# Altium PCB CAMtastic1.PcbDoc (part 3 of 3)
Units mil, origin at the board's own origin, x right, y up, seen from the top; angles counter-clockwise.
Board outline 2031.62 x 893.83 mil, 4 copper layers (Top Layer, Mid-Layer 1, Mid-Layer 2, Bottom Layer); 0 components, 63 nets, 248 pads, 0 vias.
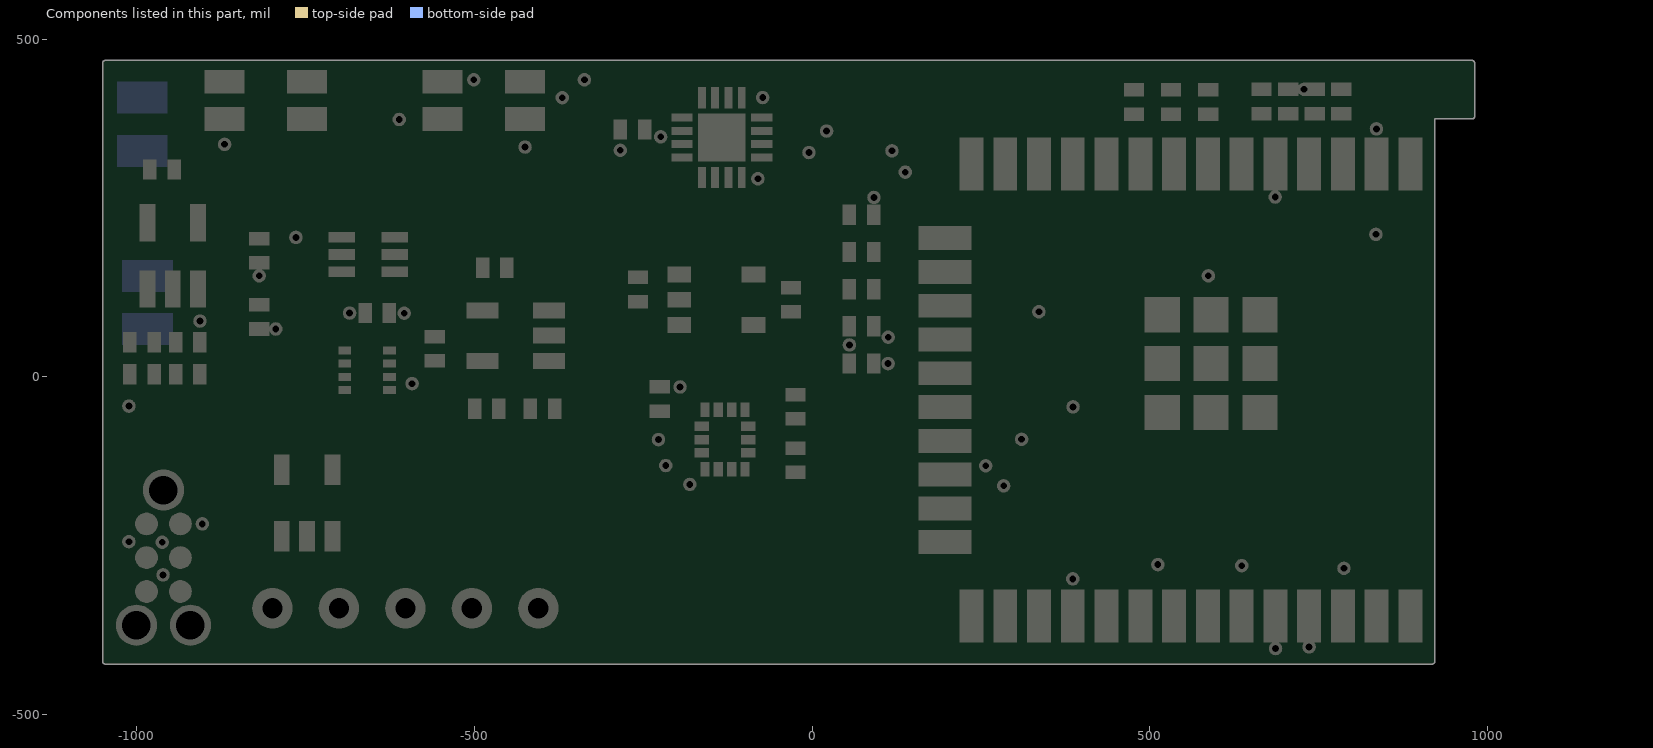
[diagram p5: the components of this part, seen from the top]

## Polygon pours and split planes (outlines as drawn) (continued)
no net on Mid-Layer 1 (solid, pour order 33): -816.2,-383.52 -782.23,-383.52 -758.21,-359.5 -758.21,-325.54 -782.23,-301.52 -816.2,-301.52 -840.21,-325.54 -840.21,-359.5
no net on Mid-Layer 1 (solid, pour order 32): -1001.14,-150.94 -1001.14,-184.5 -977.41,-208.23 -943.85,-208.23 -920.12,-184.5 -920.12,-150.94 -943.85,-127.21 -977.41,-127.21
$Net11 on Mid-Layer 1 (solid, pour order 31): 44 vertices, not listed, extent -1032.68,-407.26 962.94,450.57
no net on Mid-Layer 1 (solid, pour order 30): 503.53,-298 520.1,-298 531.81,-286.29 531.81,-269.72 520.1,-258 503.53,-258 491.81,-269.72 491.81,-286.29
no net on Mid-Layer 1 (solid, pour order 29): -1020.1,-264.09 -1003.53,-264.09 -991.81,-252.38 -991.81,-235.81 -1003.53,-224.09 -1020.1,-224.09 -1031.81,-235.81 -1031.81,-252.38
no net on Mid-Layer 1 (solid, pour order 28): 779.12,-303.46 795.69,-303.46 807.4,-291.75 807.4,-275.18 795.69,-263.47 779.12,-263.47 767.4,-275.18 767.4,-291.75
no net on Mid-Layer 1 (solid, pour order 27): 627.73,-299.53 644.3,-299.53 656.01,-287.81 656.01,-271.24 644.3,-259.53 627.73,-259.53 616.02,-271.24 616.02,-287.81
no net on Mid-Layer 1 (solid, pour order 26): 132.48,67.05 132.48,50.48 121.12,39.12 132.33,27.91 132.33,11.34 120.62,-0.37 104.05,-0.37 92.33,11.34 92.33,27.91 103.69,39.27 92.48,50.48 92.48,67.05 104.2,78.77 120.76,78.77
no net on Mid-Layer 1 (solid, pour order 25): 12.99,344.01 29.56,344.01 41.28,355.72 41.28,372.29 29.56,384.01 12.99,384.01 1.28,372.29 1.28,355.72
no net on Mid-Layer 1 (solid, pour order 24): -13.06,312.17 3.51,312.17 15.23,323.89 15.23,340.45 3.51,352.17 -13.06,352.17 -24.77,340.45 -24.77,323.89
no net on Mid-Layer 1 (solid, pour order 23): 17 vertices, not listed, extent 98.11,283.15 157.79,354.65
no net on Mid-Layer 1 (solid, pour order 22): 677.25,246.32 693.82,246.32 705.53,258.04 705.53,274.61 693.82,286.32 677.25,286.32 665.53,274.61 665.53,258.04
no net on Mid-Layer 1 (solid, pour order 21): 83.18,245.6 99.75,245.6 111.46,257.32 111.46,273.88 99.75,285.6 83.18,285.6 71.47,273.88 71.47,257.32
no net on Mid-Layer 1 (solid, pour order 20): -433.49,320.32 -416.92,320.32 -405.21,332.04 -405.21,348.61 -416.92,360.32 -433.49,360.32 -445.21,348.61 -445.21,332.04
no net on Mid-Layer 1 (solid, pour order 19): -88.65,273.32 -72.08,273.32 -60.36,285.04 -60.36,301.6 -72.08,313.32 -88.65,313.32 -100.36,301.6 -100.36,285.04
no net on Mid-Layer 2 (solid, pour order 116): 627.73,-299.53 644.3,-299.53 656.01,-287.81 656.01,-271.24 644.3,-259.53 627.73,-259.53 616.02,-271.24 616.02,-287.81
no net on Mid-Layer 2 (solid, pour order 115): 779.12,-303.46 795.69,-303.46 807.4,-291.75 807.4,-275.18 795.69,-263.47 779.12,-263.47 767.4,-275.18 767.4,-291.75
no net on Mid-Layer 2 (solid, pour order 114): -1020.1,-264.09 -1003.53,-264.09 -991.81,-252.38 -991.81,-235.81 -1003.53,-224.09 -1020.1,-224.09 -1031.81,-235.81 -1031.81,-252.38
no net on Mid-Layer 2 (solid, pour order 113): 503.53,-298 520.1,-298 531.81,-286.29 531.81,-269.72 520.1,-258 503.53,-258 491.81,-269.72 491.81,-286.29
$Net0 on Mid-Layer 2 (solid, pour order 112): 44 vertices, not listed, extent -1032.68,-407.26 962.94,450.57
no net on Mid-Layer 2 (solid, pour order 111): -1001.14,-150.94 -1001.14,-184.5 -977.41,-208.23 -943.85,-208.23 -920.12,-184.5 -920.12,-150.94 -943.85,-127.21 -977.41,-127.21
no net on Mid-Layer 2 (solid, pour order 110): -717.77,-383.52 -683.8,-383.52 -659.79,-359.5 -659.79,-325.54 -683.8,-301.52 -717.77,-301.52 -741.79,-325.54 -741.79,-359.5
no net on Mid-Layer 2 (solid, pour order 109): -619.34,-383.52 -585.38,-383.52 -561.36,-359.5 -561.36,-325.54 -585.38,-301.52 -619.34,-301.52 -643.36,-325.54 -643.36,-359.5
no net on Mid-Layer 2 (solid, pour order 108): -520.92,-383.52 -486.95,-383.52 -462.94,-359.5 -462.94,-325.54 -486.95,-301.52 -520.92,-301.52 -544.94,-325.54 -544.94,-359.5
no net on Mid-Layer 2 (solid, pour order 107): -422.49,-383.52 -388.53,-383.52 -364.51,-359.5 -364.51,-325.54 -388.53,-301.52 -422.49,-301.52 -446.51,-325.54 -446.51,-359.5
no net on Mid-Layer 2 (solid, pour order 106): 724.2,415.76 732.49,415.76 738.35,421.62 738.35,429.91 732.49,435.76 724.2,435.76 718.35,429.91 718.35,421.62
no net on Mid-Layer 2 (solid, pour order 105): 831.36,357.15 839.65,357.15 845.5,363.01 845.5,371.29 839.65,377.15 831.36,377.15 825.5,371.29 825.5,363.01
no net on Mid-Layer 2 (solid, pour order 104): -615.66,371.09 -607.38,371.09 -601.52,376.95 -601.52,385.23 -607.38,391.09 -615.66,391.09 -621.52,385.23 -621.52,376.95
no net on Mid-Layer 2 (solid, pour order 103): -874.2,334.25 -865.92,334.25 -860.06,340.11 -860.06,348.39 -865.92,354.25 -874.2,354.25 -880.06,348.39 -880.06,340.11
no net on Mid-Layer 2 (solid, pour order 102): -907.2,-227.79 -898.92,-227.79 -893.06,-221.93 -893.06,-213.65 -898.92,-207.79 -907.2,-207.79 -913.06,-213.65 -913.06,-221.93
no net on Mid-Layer 2 (solid, pour order 101): -199.86,-25.01 -191.57,-25.01 -185.71,-19.16 -185.71,-10.87 -191.57,-5.01 -199.86,-5.01 -205.71,-10.87 -205.71,-19.16
no net on Mid-Layer 2 (solid, pour order 100): 50.98,37.24 59.26,37.24 65.12,43.1 65.12,51.39 59.26,57.24 50.98,57.24 45.12,51.39 45.12,43.1
no net on Mid-Layer 2 (solid, pour order 99): -914.84,62.68 -898.27,62.68 -886.55,74.39 -886.55,90.96 -898.27,102.68 -914.84,102.68 -926.55,90.96 -926.55,74.39
no net on Mid-Layer 2 (solid, pour order 98): -802.62,50.87 -786.05,50.87 -774.34,62.58 -774.34,79.15 -786.05,90.87 -802.62,90.87 -814.33,79.15 -814.33,62.58
no net on Mid-Layer 2 (solid, pour order 97): -689.18,84.49 -680.9,84.49 -675.04,90.35 -675.04,98.63 -680.9,104.49 -689.18,104.49 -695.04,98.63 -695.04,90.35
no net on Mid-Layer 2 (solid, pour order 96): -600.75,-30.03 -584.18,-30.03 -572.46,-18.31 -572.46,-1.74 -584.18,9.97 -600.75,9.97 -612.46,-1.74 -612.46,-18.31
no net on Mid-Layer 2 (solid, pour order 95): -81.69,393.63 -65.12,393.63 -53.4,405.34 -53.4,421.91 -65.12,433.63 -81.69,433.63 -93.4,421.91 -93.4,405.34
no net on Mid-Layer 2 (solid, pour order 94): -378.36,393.39 -361.79,393.39 -350.08,405.1 -350.08,421.67 -361.79,433.39 -378.36,433.39 -390.08,421.67 -390.08,405.1
no net on Mid-Layer 2 (solid, pour order 93): -228.55,345.38 -220.27,345.38 -214.41,351.24 -214.41,359.52 -220.27,365.38 -228.55,365.38 -234.41,359.52 -234.41,351.24
no net on Mid-Layer 2 (solid, pour order 92): 377.54,-319.21 394.11,-319.21 405.83,-307.5 405.83,-290.93 394.11,-279.21 377.54,-279.21 365.83,-290.93 365.83,-307.5
no net on Mid-Layer 2 (solid, pour order 91): -969.51,-313.31 -952.94,-313.31 -941.23,-301.59 -941.23,-285.02 -952.94,-273.31 -969.51,-273.31 -981.23,-285.02 -981.23,-301.59
no net on Mid-Layer 2 (solid, pour order 90): -970.76,-264.91 -954.19,-264.91 -942.48,-253.19 -942.48,-236.62 -954.19,-224.91 -970.76,-224.91 -982.48,-236.62 -982.48,-253.19
no net on Mid-Layer 2 (solid, pour order 89): -816.2,-383.52 -782.23,-383.52 -758.21,-359.5 -758.21,-325.54 -782.23,-301.52 -816.2,-301.52 -840.21,-325.54 -840.21,-359.5
no net on Mid-Layer 2 (solid, pour order 88): 17 vertices, not listed, extent -247.65,-151.27 -196.87,-72.85
no net on Mid-Layer 2 (solid, pour order 87): 17 vertices, not listed, extent 236.91,-181.42 303.46,-111.72
no net on Mid-Layer 2 (solid, pour order 86): -189.55,-179.32 -172.98,-179.32 -161.26,-167.6 -161.26,-151.03 -172.98,-139.32 -189.55,-139.32 -201.26,-151.03 -201.26,-167.6
no net on Mid-Layer 2 (solid, pour order 85): 301.75,-112.45 318.32,-112.45 330.04,-100.73 330.04,-84.16 318.32,-72.45 301.75,-72.45 290.04,-84.16 290.04,-100.73
no net on Mid-Layer 2 (solid, pour order 84): -292.45,315.44 -275.88,315.44 -264.16,327.15 -264.16,343.72 -275.88,355.43 -292.45,355.43 -304.16,343.72 -304.16,327.15
no net on Mid-Layer 2 (solid, pour order 83): 826.36,190.98 842.93,190.98 854.65,202.7 854.65,219.27 842.93,230.98 826.36,230.98 814.65,219.27 814.65,202.7
no net on Mid-Layer 2 (solid, pour order 82): -772.78,186.49 -756.22,186.49 -744.5,198.2 -744.5,214.77 -756.22,226.48 -772.78,226.48 -784.5,214.77 -784.5,198.2
no net on Mid-Layer 2 (solid, pour order 81): -1020.1,-63.31 -1003.53,-63.31 -991.81,-51.59 -991.81,-35.02 -1003.53,-23.31 -1020.1,-23.31 -1031.81,-35.02 -1031.81,-51.59
no net on Mid-Layer 2 (solid, pour order 80): 377.91,-64.46 394.48,-64.46 406.19,-52.75 406.19,-36.18 394.48,-24.46 377.91,-24.46 366.19,-36.18 366.19,-52.75
no net on Mid-Layer 2 (solid, pour order 79): -827.18,129.61 -810.61,129.61 -798.9,141.32 -798.9,157.89 -810.61,169.61 -827.18,169.61 -838.9,157.89 -838.9,141.32
no net on Mid-Layer 2 (solid, pour order 78): 578.33,129.61 594.9,129.61 606.61,141.32 606.61,157.89 594.9,169.61 578.33,169.61 566.61,157.89 566.61,141.32
no net on Mid-Layer 2 (solid, pour order 77): -612.41,74.25 -595.84,74.25 -584.13,85.96 -584.13,102.53 -595.84,114.25 -612.41,114.25 -624.13,102.53 -624.13,85.96
no net on Mid-Layer 2 (solid, pour order 76): 327.37,76.4 343.94,76.4 355.66,88.12 355.66,104.68 343.94,116.4 327.37,116.4 315.66,104.68 315.66,88.12
no net on Mid-Layer 2 (solid, pour order 75): -88.65,273.32 -72.08,273.32 -60.36,285.04 -60.36,301.6 -72.08,313.32 -88.65,313.32 -100.36,301.6 -100.36,285.04
no net on Mid-Layer 2 (solid, pour order 74): -433.49,320.32 -416.92,320.32 -405.21,332.04 -405.21,348.61 -416.92,360.32 -433.49,360.32 -445.21,348.61 -445.21,332.04
no net on Mid-Layer 2 (solid, pour order 73): 83.18,245.6 99.75,245.6 111.46,257.32 111.46,273.88 99.75,285.6 83.18,285.6 71.47,273.88 71.47,257.32
no net on Mid-Layer 2 (solid, pour order 72): 677.25,246.32 693.82,246.32 705.53,258.04 705.53,274.61 693.82,286.32 677.25,286.32 665.53,274.61 665.53,258.04
no net on Mid-Layer 2 (solid, pour order 71): 17 vertices, not listed, extent 98.11,283.15 157.79,354.65
no net on Mid-Layer 2 (solid, pour order 70): -13.06,312.17 3.51,312.17 15.23,323.89 15.23,340.45 3.51,352.17 -13.06,352.17 -24.77,340.45 -24.77,323.89
no net on Mid-Layer 2 (solid, pour order 69): 12.99,344.01 29.56,344.01 41.28,355.72 41.28,372.29 29.56,384.01 12.99,384.01 1.28,372.29 1.28,355.72
no net on Mid-Layer 2 (solid, pour order 68): 132.48,67.05 132.48,50.48 121.12,39.12 132.33,27.91 132.33,11.34 120.62,-0.37 104.05,-0.37 92.33,11.34 92.33,27.91 103.69,39.27 92.48,50.48 92.48,67.05 104.2,78.77 120.76,78.77
$Net11 on Top Layer (solid, pour order 138): -763.03,-292.17 -763.03,-320.72 -779.21,-304.54 -779.21,-268.86 -739.72,-268.86
$Net11 on Top Layer (solid, pour order 137): -958.56,-277.21 -958.47,-277.31 -962.79,-277.31 -962.7,-277.21 -962.7,-260.91 -958.56,-260.91
$Net11 on Top Layer (solid, pour order 136): -115.31,-90.12 -115.31,-116.18 -142.95,-116.18 -142.95,-69.65 -115.31,-69.65
$Net11 on Top Layer (solid, pour order 135): -61.65,-72.81 -57.26,-77.2 -50.8,-77.2 -50.8,-83.2 -44.8,-83.2 -44.8,-84.51 -50.8,-84.51 -50.8,-97.6 -73.66,-97.6 -73.66,-62.75 -71.71,-62.75
$Net11 on Top Layer (solid, pour order 134): -926.55,90.96 -926.55,77.18 -959.18,77.18 -959.18,80.58 -969.34,90.74 -969.34,92.36 -926.55,92.36
$Net11 on Top Layer (solid, pour order 133): 268.46,206.39 268.46,156.03 254.1,170.39 245.83,170.39 245.83,229.02
$Net11 on Top Layer (solid, pour order 132): 903.89,-407.26 755.7,-407.26 755.7,-403.7 903.89,-403.7
no net on Top Layer (solid, pour order 131): -114.33,54.96 -58.9,54.96 -58.9,98.58 -114.33,98.58
no net on Top Layer (solid, pour order 130): 481.93,-16.58 481.93,-88.94 554.29,-88.94 554.29,-16.58
no net on Top Layer (solid, pour order 129): 481.93,55.87 481.93,-16.5 554.29,-16.5 554.29,55.87
no net on Top Layer (solid, pour order 128): 481.93,128.31 481.93,55.95 554.29,55.95 554.29,128.31
no net on Top Layer (solid, pour order 127): 554.37,-16.58 554.37,-88.94 626.73,-88.94 626.73,-16.58
no net on Top Layer (solid, pour order 126): 554.37,55.87 554.37,-16.5 626.73,-16.5 626.73,55.87
no net on Top Layer (solid, pour order 125): 554.37,128.31 554.37,55.95 626.73,55.95 626.73,128.31
no net on Top Layer (solid, pour order 124): 626.81,-16.58 626.81,-88.94 699.17,-88.94 699.17,-16.58
no net on Top Layer (solid, pour order 123): 626.81,55.87 626.81,-16.5 699.17,-16.5 699.17,55.87
no net on Top Layer (solid, pour order 122): 626.81,128.31 626.81,55.95 699.17,55.95 699.17,128.31
$Net11 on Top Layer (solid, pour order 121): 361 vertices, not listed, extent -801.15,-374.15 903.89,404.91
no net on Top Layer (solid, pour order 120): -923.88,281.09 -969.25,281.09 -969.25,265.91 -962.44,265.91 -962.44,190.79 -1006.06,190.79 -1006.06,265.91 -999.25,265.91 -999.25,281.09 -1001.88,281.09 -1001.88,333.09 -923.88,333.09
$Net11 on Top Layer (solid, pour order 119): 271 vertices, not listed, extent -1032.68,-351.17 770.83,450.57
$Net11 on Top Layer (solid, pour order 118): 19 vertices, not listed, extent 756.65,364.33 962.94,450.57
$Net11 on Top Layer (solid, pour order 117): 71 vertices, not listed, extent -733.03,310.28 -179.29,450.57

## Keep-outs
Keep-Out Layer:
  lines w8: -1046.68,-421.26 -1046.68,464.57 976.94,464.57 976.94,385.83 917.89,385.83 917.89,-421.26 -1046.68,-421.26

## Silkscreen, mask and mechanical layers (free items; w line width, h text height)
Top Overlay:
  drawing of 1200 lines, arcs and shapes, not listed
Bottom Overlay:
  drawing of 201 lines, arcs and shapes, not listed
